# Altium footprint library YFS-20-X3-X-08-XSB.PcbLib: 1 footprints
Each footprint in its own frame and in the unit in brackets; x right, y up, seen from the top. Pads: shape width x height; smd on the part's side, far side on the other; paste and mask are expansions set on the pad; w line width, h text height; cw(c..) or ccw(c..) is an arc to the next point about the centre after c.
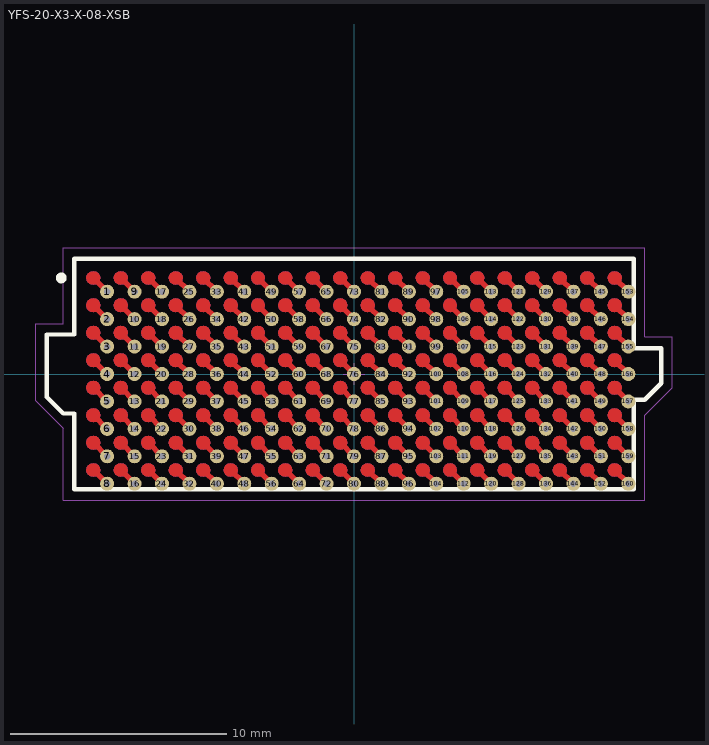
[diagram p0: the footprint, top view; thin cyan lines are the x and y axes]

## YFS-20-X3-X-08-XSB [mm] "1.27mm pitch, 160 pin, socket array; 8 rows"
height 3.4
pads (160):
  round 0.65 hole 0.3 unplated mask+0: 1(-11.43,3.81) 2(-11.43,2.54) 3(-11.43,1.27) 4(-11.43,0) 5(-11.43,-1.27) 6(-11.43,-2.54) 7(-11.43,-3.81) 8(-11.43,-5.08) 9(-10.16,3.81) 10(-10.16,2.54) 11(-10.16,1.27) 12(-10.16,0) 13(-10.16,-1.27) 14(-10.16,-2.54) 15(-10.16,-3.81) 16(-10.16,-5.08) 17(-8.89,3.81) 18(-8.89,2.54) 19(-8.89,1.27) 20(-8.89,0) 21(-8.89,-1.27) 22(-8.89,-2.54) 23(-8.89,-3.81) 24(-8.89,-5.08) 25(-7.62,3.81) 26(-7.62,2.54) 27(-7.62,1.27) 28(-7.62,0) 29(-7.62,-1.27) 30(-7.62,-2.54) 31(-7.62,-3.81) 32(-7.62,-5.08) 33(-6.35,3.81) 34(-6.35,2.54) 35(-6.35,1.27) 36(-6.35,0) 37(-6.35,-1.27) 38(-6.35,-2.54) 39(-6.35,-3.81) 40(-6.35,-5.08) 41(-5.08,3.81) 42(-5.08,2.54) 43(-5.08,1.27) 44(-5.08,0) 45(-5.08,-1.27) 46(-5.08,-2.54) 47(-5.08,-3.81) 48(-5.08,-5.08) 49(-3.81,3.81) 50(-3.81,2.54) 51(-3.81,1.27) 52(-3.81,0) 53(-3.81,-1.27) 54(-3.81,-2.54) 55(-3.81,-3.81) 56(-3.81,-5.08) 57(-2.54,3.81) 58(-2.54,2.54) 59(-2.54,1.27) 60(-2.54,0) 61(-2.54,-1.27) 62(-2.54,-2.54) 63(-2.54,-3.81) 64(-2.54,-5.08) 65(-1.27,3.81) 66(-1.27,2.54) 67(-1.27,1.27) 68(-1.27,0) 69(-1.27,-1.27) 70(-1.27,-2.54) 71(-1.27,-3.81) 72(-1.27,-5.08) 73(0,3.81) 74(0,2.54) 75(0,1.27) 76(0,0) 77(0,-1.27) 78(0,-2.54) 79(0,-3.81) 80(0,-5.08) 81(1.27,3.81) 82(1.27,2.54) 83(1.27,1.27) 84(1.27,0) 85(1.27,-1.27) 86(1.27,-2.54) 87(1.27,-3.81) 88(1.27,-5.08) 89(2.54,3.81) 90(2.54,2.54) 91(2.54,1.27) 92(2.54,0) 93(2.54,-1.27) 94(2.54,-2.54) 95(2.54,-3.81) 96(2.54,-5.08) 97(3.81,3.81) 98(3.81,2.54) 99(3.81,1.27) 100(3.81,0) 101(3.81,-1.27) 102(3.81,-2.54) 103(3.81,-3.81) 104(3.81,-5.08) 105(5.08,3.81) 106(5.08,2.54) 107(5.08,1.27) 108(5.08,0) 109(5.08,-1.27) 110(5.08,-2.54) 111(5.08,-3.81) 112(5.08,-5.08) 113(6.35,3.81) 114(6.35,2.54) 115(6.35,1.27) 116(6.35,0) 117(6.35,-1.27) 118(6.35,-2.54) 119(6.35,-3.81) 120(6.35,-5.08) 121(7.62,3.81) 122(7.62,2.54) 123(7.62,1.27) 124(7.62,0) 125(7.62,-1.27) 126(7.62,-2.54) 127(7.62,-3.81) 128(7.62,-5.08) 129(8.89,3.81) 130(8.89,2.54) 131(8.89,1.27) 132(8.89,0) 133(8.89,-1.27) 134(8.89,-2.54) 135(8.89,-3.81) 136(8.89,-5.08) 137(10.16,3.81) 138(10.16,2.54) 139(10.16,1.27) 140(10.16,0) 141(10.16,-1.27) 142(10.16,-2.54) 143(10.16,-3.81) 144(10.16,-5.08) 145(11.43,3.81) 146(11.43,2.54) 147(11.43,1.27) 148(11.43,0) 149(11.43,-1.27) 150(11.43,-2.54) 151(11.43,-3.81) 152(11.43,-5.08) 153(12.7,3.81) 154(12.7,2.54) 155(12.7,1.27) 156(12.7,0) 157(12.7,-1.27) 158(12.7,-2.54) 159(12.7,-3.81) 160(12.7,-5.08)
Top Layer:
  drawing of 320 lines, arcs and shapes, not listed
Top Overlay:
  circle w0.25: c-13.554,4.45 r0.125
  lines w0.2: -14.224,-1.067 -14.224,1.829 -12.954,1.829 -12.954,5.334 12.954,5.334 12.954,1.194 14.224,1.194 14.224,-0.432 13.462,-1.194 12.954,-1.194 12.954,-5.334 -12.954,-5.334 -12.954,-1.829 -13.462,-1.829 -14.224,-1.067
Top Paste:
  drawing of 160 lines, arcs and shapes, not listed
Top Solder:
  drawing of 160 lines, arcs and shapes, not listed
Mechanical 12:
  lines w0.001: -14.224,-1.067 -14.224,1.829 -12.954,1.829 -12.954,5.334 12.954,5.334 12.954,1.194 14.224,1.194 14.224,-0.432 13.462,-1.194 12.954,-1.194 12.954,-5.334 -12.954,-5.334 -12.954,-1.829 -13.462,-1.829 -14.224,-1.067
Mechanical 13:
  drawing of 174 lines, arcs and shapes, not listed
  text ".Designator" at 0,0 h1.52
Mechanical 15:
  lines w0.05: -0.5,0 0.5,0 ; 0,-0.5 0,0.5 ; -14.732,-1.245 -14.732,2.337 -13.462,2.337 -13.462,5.842 13.462,5.842 13.462,1.727 14.732,1.727 14.732,-0.635 13.462,-1.905 13.462,-5.842 -13.462,-5.842 -13.462,-2.515 -14.732,-1.245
